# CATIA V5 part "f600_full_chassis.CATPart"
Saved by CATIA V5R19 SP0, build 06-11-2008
Part number: F600-2000000_AllCATPart
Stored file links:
  E:\F600-Full Chassis.CATPart
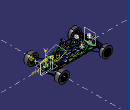
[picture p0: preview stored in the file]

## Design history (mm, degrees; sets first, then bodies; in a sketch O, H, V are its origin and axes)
Set1
  3DDatum1 "Solid.1"
  3DDatum2 "Solid.2"
Set2 "Front Suspension ASM\\RC-FRONT LOWER CONTROL ARM\\Hardpoints link with layout"
  Point1 "Lwr ball jt": stored without definition
  Point2 "LCA frnt bush": stored without definition
  Point3 "LCA rear bush": stored without definition
  Point4 "Shock lwr bush": stored without definition
  Point5 "Push rod lower point": stored without definition
Set3 "Front Suspension ASM\\Bell Crank\\Hardpoints link with seed part"
  Point6 "Shock lwr bush": stored without definition
  Point7 "Bell Crank Pivot": stored without definition
  Point8 "Push rod upper point": stored without definition
Set4 "Rear Suspension\\RC-REAR SHOCK ABSORBER\\Hardpoints link with layout"
  Point9 "Shock upr bush": stored without definition
  Point10 "Shock lwr bush": stored without definition
  Line1 "Line.5": stored without definition
Set5 "Rear Suspension\\DRIVING SHAFT POSITION PARTS\\Hardpoints link with layout"
  Point11 "drive_shaft_inner_point": stored without definition
  Point12 "Wheel Center": stored without definition
Set6 "Rear Suspension\\DRIVING SHAFT POSITION PARTS\\Geometrical Set.2"
  Line2 "Line.1": stored without definition
  Line3 "Line.2": stored without definition
  Line4 "Line.3": stored without definition
Set7 "Rear Suspension\\REAR-DAMPER-PUSH-ROD-SIN\\External References"
  Point13 "Push rod upr jt": stored without definition
  Point14 "Push rod lwr jt": stored without definition
Set8 "Steering System ASM\\XX---XXXXXXX---THREE SPOKE STEERING WHEEL\\Local Surface"
  DatumSurface1 "Sweep.1"
Set9 "Steering System ASM\\XX---XXXXXXX---STEERING MACHINE\\Isolated External References"
  Point15 "Inr Tierod ball jt": stored without definition
  Point16 "Rack Housing end": stored without definition
Set10 "Steering System ASM\\XX---XXXXXXX---STEERING MACHINE\\Temp Reference element"
  Point17 "Point.14": stored without definition
Set11 "Steering System ASM\\XX---XXXXXXX---STEERING MACHINE\\Reference Plane"
  Plane1 "Plane.2": stored without definition
Set12 "Kit_Buggy_Power Unit.1\\513MHA-1701500_ASM_AllCATPart.1\\Geometrical Set.1"
  Line5 "Axis.1": stored without definition
  Line6 "Axis.2": stored without definition
  Line7 "Axis.3": stored without definition
  Plane2 "Plane.1": stored without definition
  Plane3 "Plane.2": stored without definition
  Point18 "Intersect.1": stored without definition
  Plane4 "Plane.3": stored without definition
Set13 "Kit_Buggy_Power Unit.1\\motorpart.1\\Geometrical Set.1"
  Plane5 "Plane.1": stored without definition
Body1 (main body)
Body2 "Frame ASM\\Driving Case Front Lower Y Beam\\Driving Case Front Lower Y Beam"
  Solid1: solid without history
Body3 "Frame ASM\\Driving Case Middle Lower Y Beam\\Driving Case Middle Lower Y Beam"
  Solid2 "Solid.1": solid without history
Body4 "Frame ASM\\Driving Case Rear Lower Y Beam\\Driving Case Rear Lower Y Beam"
  Solid3 "Solid.1": solid without history
Body5 "Frame ASM\\Engine Room Middle Lower Y Beam-1\\Engine Room Middle Lower Y Beam-1"
  Solid4 "Solid.1": solid without history
Body6 "Frame ASM\\Engine Room Rear Lower Y Beam\\Engine Room Rear Lower Y Beam"
  Solid5 "Solid.1": solid without history
Body7 "Frame ASM\\Driving Case Lower Side Beam\\Driving Case Lower Side Beam"
  Solid6 "Solid.1": solid without history
Body8 "Frame ASM\\Engine Room Lower Side Beam\\Engine Room Lower Side Beam"
  Solid7 "Solid.1": solid without history
Body9 "Frame ASM\\Floor Rear Cross Stiffer\\Floor Rear Cross Stiffer"
  Solid8 "Solid.1": solid without history
Body10 "Frame ASM\\Safe Cage Rear Main Beam\\Safe Cage Rear Main Beam"
  Solid9 "Solid.1": solid without history
Body11 "Frame ASM\\Driving Case Rear Upper Y Beam\\Driving Case Rear Upper Y Beam"
  Solid10 "Solid.1": solid without history
Body12 "Frame ASM\\Safe Cage Rear Upper Cross Stiffer\\Safe Cage Rear Upper Cross Stiffer"
  Solid11 "Solid.2": solid without history
Body13 "Frame ASM\\Safe Cage Rear Lower Cross Stiffer\\Safe Cage Rear Lower Cross Stiffer"
  Solid12 "Solid.1": solid without history
Body14 "Frame ASM\\Safe Cage Front Main Frame\\Safe Cage Front Main Frame"
  Solid13 "Solid.1": solid without history
Body15 "Frame ASM\\Safe Cage Roof Y Beam\\Safe Cage Roof Y Beam"
  Solid14 "Solid.1": solid without history
Body16 "Frame ASM\\Safe Cage Front Y Beam\\Safe Cage Front Y Beam"
  Solid15 "Solid.1": solid without history
Body17 "Frame ASM\\Safe Cage Front Y Beam\\Bell Crank Support"
  Solid16 "Solid.1": solid without history
Body18 "Frame ASM\\Driving Case Front Upper Y Beam\\Driving Case Front Upper Y Beam"
  Solid17 "Solid.1": solid without history
Body19 "Frame ASM\\Engine Room Upper Side Beam\\Engine Room Upper Side Beam"
  Solid18 "Solid.1": solid without history
Body20 "Frame ASM\\Rear Back Bone Beam\\Rear Back Bone Beam"
  Solid19 "Solid.1": solid without history
Body21 "Frame ASM\\Rear Shocks Fixing Beam\\Rear Shocks Fixing Beam"
  Solid20 "Solid.4": solid without history
Body22 "Frame ASM\\Engine Room Middle Y Beam-3\\Engine Room Middle Y Beam-3"
  Solid21 "Solid.1": solid without history
Body23 "Frame ASM\\Engine Room Side Stiffer-3\\Engine Room Side Stiffer-3"
  Solid22 "Solid.1": solid without history
Body24 "Frame ASM\\Front Control Arm Lower Support\\Front Control Arm Lower Support"
  Solid23 "Solid.1": solid without history
Body25 "Frame ASM\\Driving Case Upper Side Beam\\Driving Case Upper Side Beam"
  Solid24 "Solid.1": solid without history
Body26 "Frame ASM\\Driving Case Front Z Beam\\Driving Case Front Z Beam"
  Solid25 "Solid.1": solid without history
Body27 "Frame ASM\\Driving Case Side Stiffer-1\\Driving Case Side Stiffer-1"
  Solid26 "Solid.1": solid without history
Body28 "Frame ASM\\Driving Case Middle Z Beam\\Driving Case Middle Z Beam"
  Solid27 "Solid.1": solid without history
Body29 "Frame ASM\\Driving Case Side Stiffer-2\\Driving Case Side Stiffer-2"
  Solid28 "Solid.1": solid without history
Body30 "Frame ASM\\Driving Case Side Stiffer-3\\Driving Case Side Stiffer-3"
  Solid29 "Solid.1": solid without history
Body31 "Frame ASM\\Safe Cage Front Stiffer-1\\Safe Cage Front Stiffer-1"
  Solid30 "Solid.1": solid without history
Body32 "Frame ASM\\Safe Cage Front Stiffer-2\\Safe Cage Front Stiffer-2"
  Solid31 "Solid.1": solid without history
Body33 "Frame ASM\\Safe Cage Front Stiffer-3\\Safe Cage Front Stiffer-3"
  Solid32 "Solid.1": solid without history
Body34 "Frame ASM\\Front Control Arm Support Stiffer\\Front Control Arm Support Stiffer"
  Solid33 "Solid.1": solid without history
Body35 "Frame ASM\\Shock Absorber Support\\Shock Absorber Support"
  Solid34 "Solid.1": solid without history
Body36 "Frame ASM\\Engine Room Middle Z Beam\\Engine Room Middle Z Beam"
  Solid35 "Solid.1": solid without history
Body37 "Frame ASM\\Engine Room Middle Y Beam-2\\Engine Room Middle Y Beam-2"
  Solid36 "Solid.1": solid without history
Body38 "Frame ASM\\Engine Room Side Sitffer-1\\Engine Room Side Sitffer-1"
  Solid37 "Solid.1": solid without history
Body39 "Frame ASM\\Final Gear Case Front Plate\\Final Gear Case Front Plate"
  Solid38 "Solid.1": solid without history
Body40 "Frame ASM\\Final Gear Case Rear Plate\\Final Gear Case Rear Plate"
  Solid39 "Solid.1": solid without history
Body41 "Frame ASM\\Engine Room Side Stiffer-2\\Engine Room Side Stiffer-2"
  Solid40 "Solid.1": solid without history
Body42 "Frame ASM\\Front Shock Absorber Fixing Bracket\\Front Shock Absorber Fixing Bracket"
  Solid41 "Solid.1": solid without history
Body43 "Frame ASM\\Floor\\Floor"
  Solid42 "Solid.1": solid without history
Body44 "Frame ASM\\Steering Column Fixing Bracket\\Steering Column Fixing Bracket"
  Solid43 "Solid.1": solid without history
Body45 "Frame ASM\\Symmetry of Safe Cage Front Stiffer-2.1\\Safe Cage Front Stiffer-2"
  Solid44 "Solid.1": solid without history
Body46 "Frame ASM\\Symmetry of Driving Case Front Z Beam.1\\Driving Case Front Z Beam"
  Solid45 "Solid.1": solid without history
Body47 "Frame ASM\\Symmetry of Driving Case Side Stiffer-1.1\\Driving Case Side Stiffer-1"
  Solid46 "Solid.1": solid without history
Body48 "Frame ASM\\Symmetry of Driving Case Middle Z Beam.1\\Driving Case Middle Z Beam"
  Solid47 "Solid.1": solid without history
Body49 "Frame ASM\\Symmetry of Driving Case Side Stiffer-2.1\\Driving Case Side Stiffer-2"
  Solid48 "Solid.1": solid without history
Body50 "Frame ASM\\Symmetry of Driving Case Side Stiffer-3.1\\Driving Case Side Stiffer-3"
  Solid49 "Solid.1": solid without history
Body51 "Frame ASM\\Symmetry of Floor Rear Cross Stiffer.1\\Floor Rear Cross Stiffer"
  Solid50 "Solid.1": solid without history
Body52 "Frame ASM\\Symmetry of Driving Case Lower Side Beam.1\\Driving Case Lower Side Beam"
  Solid51 "Solid.1": solid without history
Body53 "Frame ASM\\Symmetry of Engine Room Lower Side Beam.1\\Engine Room Lower Side Beam"
  Solid52 "Solid.1": solid without history
Body54 "Frame ASM\\Symmetry of Safe Cage Rear Upper Cross Stiffer.1\\Safe Cage Rear Upper Cross Stiffer"
  Solid53 "Solid.1": solid without history
Body55 "Frame ASM\\Symmetry of Safe Cage Rear Lower Cross Stiffer.1\\Safe Cage Rear Lower Cross Stiffer"
  Solid54 "Solid.1": solid without history
Body56 "Frame ASM\\Symmetry of Rear Back Bone Beam.1\\Rear Back Bone Beam"
  Solid55 "Solid.1": solid without history
Body57 "Frame ASM\\Symmetry of Engine Room Middle Z Beam.1\\Engine Room Middle Z Beam"
  Solid56 "Solid.1": solid without history
Body58 "Frame ASM\\Symmetry of Engine Room Side Stiffer-3.1\\Engine Room Side Stiffer-3"
  Solid57 "Solid.1": solid without history
Body59 "Frame ASM\\Symmetry of Rear Shocks Fixing Beam.1\\Rear Shocks Fixing Beam"
  Solid58 "Solid.1": solid without history
Body60 "Frame ASM\\Symmetry of Engine Room Side Stiffer-2.1\\Engine Room Side Stiffer-2"
  Solid59 "Solid.1": solid without history
Body61 "Frame ASM\\Symmetry of Engine Room Side Sitffer-1.1\\Engine Room Side Sitffer-1"
  Solid60 "Solid.1": solid without history
Body62 "Frame ASM\\Symmetry of Steering Column Fixing Bracket.1\\Steering Column Fixing Bracket"
  Solid61 "Solid.1": solid without history
Body63 "Frame ASM\\Symmetry of Safe Cage Front Stiffer-1.1\\Safe Cage Front Stiffer-1"
  Solid62 "Solid.1": solid without history
Body64 "Frame ASM\\Symmetry of Shock Absorber Support.1\\Shock Absorber Support"
  Solid63 "Solid.1": solid without history
Body65 "Front Suspension ASM\\RC-FRONT LOWER CONTROL ARM\\Outer Bush"
  Solid64 "Solid.1": solid without history
Body66 "Front Suspension ASM\\RC-FRONT LOWER CONTROL ARM\\Lower Front Arm"
  Solid65 "Solid.1": solid without history
Body67 "Front Suspension ASM\\RC-FRONT LOWER CONTROL ARM\\Lower Rear Arm"
  Solid66 "Solid.1": solid without history
Body68 "Front Suspension ASM\\RC-FRONT LOWER CONTROL ARM\\Rear Bush"
  Solid67 "Solid.1": solid without history
Body69 "Front Suspension ASM\\RC-FRONT LOWER CONTROL ARM\\Front Bush"
  Solid68 "Solid.3": solid without history
Body70 "Front Suspension ASM\\RC-FRONT LOWER CONTROL ARM\\Shock Absorber Fixing Bracket"
  Solid69 "Solid.1": solid without history
Body71 "Front Suspension ASM\\RC-FRONT STEERING KNUCKLE\\Main Body"
  Solid70 "Solid.1": solid without history
Body72 "Front Suspension ASM\\RC-FRONT STEERING KNUCKLE\\Bearing House"
  Solid71 "Solid.1": solid without history
Body73 "Front Suspension ASM\\RC-FRONT STEERING KNUCKLE\\Body.9"
  Solid72 "Solid.1": solid without history
Body74 "Front Suspension ASM\\13-6Inch Formula Rim\\Body.1"
  Solid73 "Solid.1": solid without history
Body75 "Front Suspension ASM\\13-6Inch Formula Rim\\Body.2"
  Solid74 "Solid.1": solid without history
Body76 "Front Suspension ASM\\RC-FRONT SHOCK ABSORBER ASM\\Upper Tube"
  Solid75 "Solid.1": solid without history
Body77 "Front Suspension ASM\\RC-FRONT SHOCK ABSORBER ASM\\Lower Tube"
  Solid76 "Solid.1": solid without history
Body78 "Front Suspension ASM\\RC-FRONT SHOCK ABSORBER ASM\\Upper Spring Seat"
  Solid77 "Solid.1": solid without history
Body79 "Front Suspension ASM\\RC-FRONT SHOCK ABSORBER ASM\\Spring"
  Solid78 "Solid.1": solid without history
Body80 "Front Suspension ASM\\RC-FRONT SHOCK ABSORBER ASM\\Upper Fixing Tube"
  Solid79 "Solid.1": solid without history
Body81 "Front Suspension ASM\\RC-FRONT SHOCK ABSORBER ASM\\Lower FixingTube"
  Solid80 "Solid.1": solid without history
Body82 "Front Suspension ASM\\ATV-23-7-10\\Body.1"
  Solid81 "Solid.1": solid without history
Body83 "Front Suspension ASM\\7205B.1\\Inner Roller"
  Solid82 "Solid.1": solid without history
Body84 "Front Suspension ASM\\7205B.1\\Ball"
  Solid83 "Solid.1": solid without history
Body85 "Front Suspension ASM\\7205B.1\\Outer Roller"
  Solid84 "Solid.1": solid without history
Body86 "Front Suspension ASM\\7205B.2\\Inner Roller"
  Solid85 "Solid.1": solid without history
Body87 "Front Suspension ASM\\7205B.2\\Ball"
  Solid86 "Solid.1": solid without history
Body88 "Front Suspension ASM\\7205B.2\\Outer Roller"
  Solid87 "Solid.1": solid without history
Body89 "Front Suspension ASM\\ISO 8675 NUT M20x1.5 STEEL GRADE C HEXAGON THIN METRIC FINE.1\\BodyPartBody"
  Solid88 "Solid.1": solid without history
Body90 "Front Suspension ASM\\Front Hub\\HUB"
  Solid89 "Solid.1": solid without history
Body91 "Front Suspension ASM\\Front Rotor\\Body.1"
  Solid90 "Solid.1": solid without history
Body92 "Front Suspension ASM\\Ball Joint Shell.3\\Outer Ball Joint Shell"
  Solid91 "Solid.1": solid without history
Body93 "Front Suspension ASM\\Ball Joint Sphere.3\\BJ-Sphere"
  Solid92 "Solid.4": solid without history
Body94 "Front Suspension ASM\\RC-1000003.1\\Front Arm"
  Solid93 "Solid.1": solid without history
Body95 "Front Suspension ASM\\RC-1000003.1\\Rear Arm"
  Solid94 "Solid.1": solid without history
Body96 "Front Suspension ASM\\RC-1000003.1\\Middle tube"
  Solid95 "Solid.1": solid without history
Body97 "Front Suspension ASM\\RC-1000003.1\\Outer Ball Joint Shell"
  Solid96 "Solid.2": solid without history
Body98 "Front Suspension ASM\\Push Rod\\Push Rod"
  Solid97 "Solid.1": solid without history
Body99 "Front Suspension ASM\\Bell Crank\\Bell Crank"
  Solid98 "Solid.1": solid without history
Body100 "Front Suspension ASM\\Bell Crank\\Pivot Tube"
  Solid99 "Solid.1": solid without history
Body101 "Front Suspension ASM\\Bell Crank\\Push_Link"
  Solid100 "Solid.1": solid without history
Body102 "Rear Suspension\\RC-REAR UPPER CONTROL ARM\\Outer Ball Joint Shell"
  Solid101 "Solid.1": solid without history
Body103 "Rear Suspension\\RC-REAR UPPER CONTROL ARM\\Front Arm"
  Solid102 "Solid.9": solid without history
Body104 "Rear Suspension\\RC-REAR UPPER CONTROL ARM\\Rear Arm"
  Solid103 "Solid.1": solid without history
Body105 "Rear Suspension\\RC-REAR UPPER CONTROL ARM\\Outer Tube"
  Solid104 "Solid.22": solid without history
Body106 "Rear Suspension\\RC-REAR LOWER CONTROL ARM.1\\Outer Ball Joint Shell"
  Solid105 "Solid.1": solid without history
Body107 "Rear Suspension\\RC-REAR LOWER CONTROL ARM.1\\Front Arm"
  Solid106 "Solid.1": solid without history
Body108 "Rear Suspension\\RC-REAR LOWER CONTROL ARM.1\\Rear_Arm"
  Solid107 "Solid.1": solid without history
Body109 "Rear Suspension\\RC-REAR LOWER CONTROL ARM.1\\Rear Arm 2"
  Solid108 "Solid.1": solid without history
Body110 "Rear Suspension\\RC-REAR LOWER CONTROL ARM.1\\Middle Tube"
  Solid109 "Solid.1": solid without history
Body111 "Rear Suspension\\RC-REAR LOWER CONTROL ARM.1\\Outer Tube"
  Solid110 "Solid.34": solid without history
Body112 "Rear Suspension\\RC-REAR LOWER CONTROL ARM.1\\Outer Ball Joint Shell"
  Solid111 "Solid.1": solid without history
Body113 "Rear Suspension\\RC-REAR KNUCKLE\\Mian Body"
  Solid112 "Solid.1": solid without history
Body114 "Rear Suspension\\RC-REAR KNUCKLE\\Bearing House"
  Solid113 "Solid.1": solid without history
Body115 "Rear Suspension\\RC-REAR KNUCKLE\\Lower Tube"
  Solid114 "Solid.1": solid without history
Body116 "Rear Suspension\\RC-REAR SHOCK ABSORBER\\Upper Tube"
  Solid115 "Solid.2": solid without history
Body117 "Rear Suspension\\RC-REAR SHOCK ABSORBER\\Lower Tube"
  Solid116 "Solid.6": solid without history
Body118 "Rear Suspension\\RC-REAR SHOCK ABSORBER\\Upper Spring Seat"
  Solid117 "Solid.9": solid without history
Body119 "Rear Suspension\\RC-REAR SHOCK ABSORBER\\Spring"
  Solid118 "Solid.13": solid without history
Body120 "Rear Suspension\\RC-REAR SHOCK ABSORBER\\Upper Fixing Tube"
  Solid119 "Solid.14": solid without history
Body121 "Rear Suspension\\RC-REAR SHOCK ABSORBER\\Lower FixingTube"
  Solid120 "Solid.15": solid without history
Body122 "Rear Suspension\\WHEEL RIM\\Body.1"
  Solid121 "Solid.1": solid without history
Body123 "Rear Suspension\\WHEEL RIM\\Body.2"
  Solid122 "Solid.1": solid without history
Body124 "Rear Suspension\\XX-205-45-R16\\Body.1"
  Solid123 "Solid.1": solid without history
Body125 "Rear Suspension\\B21-3001017.1\\Body.1"
  Solid124 "Solid.1": solid without history
Body126 "Rear Suspension\\B11-2203205.1\\Body.1"
  Solid125 "Solid.1": solid without history
Body127 "Rear Suspension\\CVJT.1\\Body.1"
  Solid126 "Solid.1": solid without history
Body128 "Rear Suspension\\CVJT.1\\Dust Cover"
  Solid127 "Solid.1": solid without history
Body129 "Rear Suspension\\INNER CVJT.1\\Body.1"
  Solid128 "Solid.1": solid without history
Body130 "Rear Suspension\\INNER CVJT.1\\DustCover"
  Solid129 "Solid.1": solid without history
Body131 "Rear Suspension\\Dirving Shaft Middle Column.1\\Body.1"
  Solid130 "Solid.1": solid without history
Body132 "Rear Suspension\\Dirving Shaft Middle Column.1\\Dust Cover"
  Solid131 "Solid.1": solid without history
Body133 "Rear Suspension\\REAR-DAMPER-PUSH-ROD-SIN\\Tube"
  Solid132 "Solid.1": solid without history
Body134 "Rear Suspension\\REAR-DAMPER-BELL-CRANK-LH\\Bell Crank"
  Solid133 "Solid.1": solid without history
Body135 "Rear Suspension\\REAR-DAMPER-BELL-CRANK-LH\\Rotation Tube"
  Solid134 "Solid.1": solid without history
Body136 "Steering System ASM\\XX---XXXXXXX---THREE SPOKE STEERING WHEEL\\SPOKE"
  Solid135 "Solid.1": solid without history
Body137 "Steering System ASM\\XX---XXXXXXX---STEERING COLUMN\\Body.31"
  Solid136 "Solid.1": solid without history
Body138 "Steering System ASM\\XX---XXXXXXX---STEERING MACHINE\\PartBody"
  Solid137 "Solid.1": solid without history
Body139 "Steering System ASM\\XX---XXXXXXX---STEERING ROD\\PartBody"
  Solid138 "Solid.1": solid without history
Body140 "Steering System ASM\\Symmetry of XX---XXXXXXX---STEERING ROD.1\\PartBody"
  Solid139 "Solid.1": solid without history
Body141 "Steering System ASM\\UNIVERSAL JOINT FORK.1\\PartBody"
  Solid140 "Solid.1": solid without history
Body142 "Steering System ASM\\UNIVERSAL JOINT FORK-2.2\\PartBody"
  Solid141 "Solid.1": solid without history
Body143 "Steering System ASM\\RC-8000001-1.1\\PartBody"
  Solid142 "Solid.1": solid without history
Body144 "Steering System ASM\\RC-8000001-1.1\\Body.2"
  Solid143 "Solid.1": solid without history
Body145 "Steering System ASM\\RC-8000001-1.2\\PartBody"
  Solid144 "Solid.1": solid without history
Body146 "Steering System ASM\\RC-8000001-1.2\\Body.2"
  Solid145 "Solid.1": solid without history
Body147 "Steering System ASM\\ANGLE CONTACTED BALL BEARING-7003C\\Inner Roller"
  Solid146 "Solid.1": solid without history
Body148 "Steering System ASM\\ANGLE CONTACTED BALL BEARING-7003C\\Ball"
  Solid147 "Solid.1": solid without history
Body149 "Steering System ASM\\ANGLE CONTACTED BALL BEARING-7003C\\Outer Roller"
  Solid148 "Solid.1": solid without history
Body150 "Steering System ASM\\ANGLE CONTACTED BALL BEARING-7003C.1\\Inner Roller"
  Solid149 "Solid.1": solid without history
Body151 "Steering System ASM\\ANGLE CONTACTED BALL BEARING-7003C.1\\Ball"
  Solid150 "Solid.1": solid without history
Body152 "Steering System ASM\\ANGLE CONTACTED BALL BEARING-7003C.1\\Outer Roller"
  Solid151 "Solid.1": solid without history
Body153 "Steering System ASM\\BEARING HOUSE\\PartBody"
  Solid152 "Solid.1": solid without history
Body154 "Steering System ASM\\BEARING HOUSE.1\\PartBody"
  Solid153 "Solid.1": solid without history
Body155 "Kit_Buggy_Power Unit.1\\Differentation.1\\Chain Wheel"
  Solid154 "Solid.1": solid without history
Body156 "Kit_Buggy_Power Unit.1\\Differentation.1\\Chain"
  Solid155 "Solid.1": solid without history
Body157 "Kit_Buggy_Power Unit.1\\Differentation.1\\Connecting Flange"
  Solid156 "Solid.1": solid without history
  Sketch1 "Sketch.18", origin (2049.9819, -110.2005, 10.7859), H (-1, 0, 0), V (0, 0, 1), geometry linked from another document
Body158 "Kit_Buggy_Power Unit.1\\513MHA-1701500_ASM_AllCATPart.1\\188\\MANIFOLD_SOLID_BREP #2629297"
  Solid157 "Solid.1": solid without history
Body159 "Kit_Buggy_Power Unit.1\\513MHA-1701500_ASM_AllCATPart.1\\189\\MANIFOLD_SOLID_BREP #2647029"
  Solid158 "Solid.1": solid without history
Body160 "Kit_Buggy_Power Unit.1\\513MHA-1701500_ASM_AllCATPart.1\\190\\MANIFOLD_SOLID_BREP #2629297"
  Solid159 "Solid.1": solid without history
Body161 "Kit_Buggy_Power Unit.1\\513MHA-1701500_ASM_AllCATPart.1\\191\\MANIFOLD_SOLID_BREP #2647029"
  Solid160 "Solid.1": solid without history
Body162 "Kit_Buggy_Power Unit.1\\513MHA-1701500_ASM_AllCATPart.1\\192\\MANIFOLD_SOLID_BREP #2647293"
  Solid161 "Solid.1": solid without history
Body163 "Kit_Buggy_Power Unit.1\\513MHA-1701500_ASM_AllCATPart.1\\193\\MANIFOLD_SOLID_BREP #2647293"
  Solid162 "Solid.1": solid without history
Body164 "Kit_Buggy_Power Unit.1\\513MHA-1701500_ASM_AllCATPart.1\\194\\MANIFOLD_SOLID_BREP #2656548"
  Solid163 "Solid.1": solid without history
Body165 "Kit_Buggy_Power Unit.1\\513MHA-1701500_ASM_AllCATPart.1\\195\\MANIFOLD_SOLID_BREP #2656548"
  Solid164 "Solid.1": solid without history
Body166 "Kit_Buggy_Power Unit.1\\513MHA-1701500_ASM_AllCATPart.1\\196\\MANIFOLD_SOLID_BREP #2657716"
  Solid165 "Solid.1": solid without history
Body167 "Kit_Buggy_Power Unit.1\\513MHA-1701500_ASM_AllCATPart.1\\197\\MANIFOLD_SOLID_BREP #2658366"
  Solid166 "Solid.1": solid without history
Body168 "Kit_Buggy_Power Unit.1\\513MHA-1701500_ASM_AllCATPart.1\\211\\207\\MANIFOLD_SOLID_BREP #2711857"
  Solid167 "Solid.1": solid without history
Body169 "Kit_Buggy_Power Unit.1\\513MHA-1701500_ASM_AllCATPart.1\\211\\208\\MANIFOLD_SOLID_BREP #2712359"
  Solid168 "Solid.1": solid without history
Body170 "Kit_Buggy_Power Unit.1\\513MHA-1701500_ASM_AllCATPart.1\\211\\210\\MANIFOLD_SOLID_BREP #2714242"
  Solid169 "Solid.1": solid without history
Body171 "Kit_Buggy_Power Unit.1\\513MHA-1701500_ASM_AllCATPart.1\\212\\207\\MANIFOLD_SOLID_BREP #2711857"
  Solid170 "Solid.1": solid without history
Body172 "Kit_Buggy_Power Unit.1\\513MHA-1701500_ASM_AllCATPart.1\\212\\208\\MANIFOLD_SOLID_BREP #2712359"
  Solid171 "Solid.1": solid without history
Body173 "Kit_Buggy_Power Unit.1\\513MHA-1701500_ASM_AllCATPart.1\\212\\209\\MANIFOLD_SOLID_BREP #2712579"
  Solid172 "Solid.1": solid without history
Body174 "Kit_Buggy_Power Unit.1\\513MHA-1701500_ASM_AllCATPart.1\\212\\209\\MANIFOLD_SOLID_BREP #2712767"
  Solid173 "Solid.1": solid without history
Body175 "Kit_Buggy_Power Unit.1\\513MHA-1701500_ASM_AllCATPart.1\\212\\209\\MANIFOLD_SOLID_BREP #2712955"
  Solid174 "Solid.1": solid without history
Body176 "Kit_Buggy_Power Unit.1\\513MHA-1701500_ASM_AllCATPart.1\\212\\209\\MANIFOLD_SOLID_BREP #2713143"
  Solid175 "Solid.1": solid without history
Body177 "Kit_Buggy_Power Unit.1\\513MHA-1701500_ASM_AllCATPart.1\\212\\210\\MANIFOLD_SOLID_BREP #2714242"
  Solid176 "Solid.1": solid without history
Body178 "Kit_Buggy_Power Unit.1\\513MHA-1701500_ASM_AllCATPart.1\\Left Fixing Flange"
  Solid177 "Solid.1": solid without history
  Sketch2 "Sketch.1", origin (2049.9819, -102.0792, 10.7859), H (1, 0, 0), V (0, 0, 1), geometry linked from another document
Body179 "Kit_Buggy_Power Unit.1\\513MHA-1701500_ASM_AllCATPart.1\\Rear Braking Disc"
  Solid178 "Solid.1": solid without history
Body180 "Kit_Buggy_Power Unit.1\\513MHA-1701500_ASM_AllCATPart.1\\Left Frame"
  Solid179 "Solid.1": solid without history
Body181 "Kit_Buggy_Power Unit.1\\513MHA-1701500_ASM_AllCATPart.1\\Right Frame"
  Solid180 "Solid.1": solid without history
Body182 "Kit_Buggy_Power Unit.1\\513MHA-1701500_ASM_AllCATPart.1\\Frame Link Tube"
  Solid181 "Solid.1": solid without history
Body183 "Kit_Buggy_Power Unit.1\\513MHA-1701500_ASM_AllCATPart.1\\New Shell-Left"
  Solid182 "Solid.1": solid without history
Body184 "Kit_Buggy_Power Unit.1\\513MHA-1701500_ASM_AllCATPart.1\\New Shell-Right"
  Solid183 "Solid.22": solid without history
Body185 "Kit_Buggy_Power Unit.1\\motorpart.1\\Brep With Voids.1"
  Solid184 "Solid.1": solid without history
Body186 "Kit_Buggy_Power Unit.1\\motorpart.1\\PartBody.2"
  Solid185 "Solid.1": solid without history
Body187 "Kit_Buggy_Power Unit.1\\motorpart.1\\PartBody.4"
  Solid186 "Solid.1": solid without history
Body188 "Kit_Buggy_Power Unit.1\\motorpart.1\\PartBody.5"
  Solid187 "Solid.1": solid without history
Body189 "Kit_Buggy_Power Unit.1\\motorpart.1\\PartBody.6"
  Solid188 "Solid.1": solid without history
Body190 "Kit_Buggy_Power Unit.1\\motorpart.1\\PartBody.7"
  Solid189 "Solid.1": solid without history
Body191 "Kit_Buggy_Power Unit.1\\motorpart.1\\PartBody.8"
  Solid190 "Solid.1": solid without history
Body192 "Kit_Buggy_Power Unit.1\\motorpart.1\\New Sump"
  Solid191 "Solid.1": solid without history
Body193 "Symmetry of Rear Suspension.1\\Symmetry of RC-REAR UPPER CONTROL ARM.1\\Outer Ball Joint Shell"
  Solid192 "Solid.1": solid without history
Body194 "Symmetry of Rear Suspension.1\\Symmetry of RC-REAR UPPER CONTROL ARM.1\\Front Arm"
  Solid193 "Solid.2": solid without history
Body195 "Symmetry of Rear Suspension.1\\Symmetry of RC-REAR UPPER CONTROL ARM.1\\Rear Arm"
  Solid194 "Solid.3": solid without history
Body196 "Symmetry of Rear Suspension.1\\Symmetry of RC-REAR UPPER CONTROL ARM.1\\Outer Tube"
  Solid195 "Solid.4": solid without history
Body197 "Symmetry of Rear Suspension.1\\Symmetry of RC-REAR LOWER CONTROL ARM.1.1\\Outer Ball Joint Shell"
  Solid196 "Solid.1": solid without history
Body198 "Symmetry of Rear Suspension.1\\Symmetry of RC-REAR LOWER CONTROL ARM.1.1\\Front Arm"
  Solid197 "Solid.2": solid without history
Body199 "Symmetry of Rear Suspension.1\\Symmetry of RC-REAR LOWER CONTROL ARM.1.1\\Rear_Arm"
  Solid198 "Solid.3": solid without history
Body200 "Symmetry of Rear Suspension.1\\Symmetry of RC-REAR LOWER CONTROL ARM.1.1\\Rear Arm 2"
  Solid199 "Solid.4": solid without history
Body201 "Symmetry of Rear Suspension.1\\Symmetry of RC-REAR LOWER CONTROL ARM.1.1\\Middle Tube"
  Solid200 "Solid.5": solid without history
Body202 "Symmetry of Rear Suspension.1\\Symmetry of RC-REAR LOWER CONTROL ARM.1.1\\Outer Tube"
  Solid201 "Solid.6": solid without history
Body203 "Symmetry of Rear Suspension.1\\Symmetry of RC-REAR LOWER CONTROL ARM.1.1\\Outer Ball Joint Shell"
  Solid202 "Solid.7": solid without history
Body204 "Symmetry of Rear Suspension.1\\Symmetry of RC-REAR KNUCKLE.1\\Mian Body"
  Solid203 "Solid.1": solid without history
Body205 "Symmetry of Rear Suspension.1\\Symmetry of RC-REAR KNUCKLE.1\\Bearing House"
  Solid204 "Solid.2": solid without history
Body206 "Symmetry of Rear Suspension.1\\Symmetry of RC-REAR KNUCKLE.1\\Lower Tube"
  Solid205 "Solid.3": solid without history
Body207 "Symmetry of Rear Suspension.1\\Symmetry of RC-REAR SHOCK ABSORBER.1\\Upper Tube"
  Solid206 "Solid.1": solid without history
Body208 "Symmetry of Rear Suspension.1\\Symmetry of RC-REAR SHOCK ABSORBER.1\\Lower Tube"
  Solid207 "Solid.2": solid without history
Body209 "Symmetry of Rear Suspension.1\\Symmetry of RC-REAR SHOCK ABSORBER.1\\Upper Spring Seat"
  Solid208 "Solid.3": solid without history
Body210 "Symmetry of Rear Suspension.1\\Symmetry of RC-REAR SHOCK ABSORBER.1\\Spring"
  Solid209 "Solid.4": solid without history
Body211 "Symmetry of Rear Suspension.1\\Symmetry of RC-REAR SHOCK ABSORBER.1\\Upper Fixing Tube"
  Solid210 "Solid.5": solid without history
Body212 "Symmetry of Rear Suspension.1\\Symmetry of RC-REAR SHOCK ABSORBER.1\\Lower FixingTube"
  Solid211 "Solid.6": solid without history
Body213 "Symmetry of Rear Suspension.1\\Symmetry of WHEEL RIM.1\\Body.1"
  Solid212 "Solid.1": solid without history
Body214 "Symmetry of Rear Suspension.1\\Symmetry of WHEEL RIM.1\\Body.2"
  Solid213 "Solid.2": solid without history
Body215 "Symmetry of Rear Suspension.1\\Symmetry of XX-205-45-R16.1\\Body.1"
  Solid214 "Solid.1": solid without history
Body216 "Symmetry of Rear Suspension.1\\Symmetry of B21-3001017.1.1\\Body.1"
  Solid215 "Solid.1": solid without history
Body217 "Symmetry of Rear Suspension.1\\Symmetry of B11-2203205.1.1\\Body.1"
  Solid216 "Solid.1": solid without history
Body218 "Symmetry of Rear Suspension.1\\Symmetry of CVJT.1.1\\Body.1"
  Solid217 "Solid.1": solid without history
Body219 "Symmetry of Rear Suspension.1\\Symmetry of CVJT.1.1\\Dust Cover"
  Solid218 "Solid.2": solid without history
Body220 "Symmetry of Rear Suspension.1\\Symmetry of INNER CVJT.1.1\\Body.1"
  Solid219 "Solid.1": solid without history
Body221 "Symmetry of Rear Suspension.1\\Symmetry of INNER CVJT.1.1\\DustCover"
  Solid220 "Solid.2": solid without history
Body222 "Symmetry of Rear Suspension.1\\Symmetry of Dirving Shaft Middle Column.1.1\\Body.1"
  Solid221 "Solid.1": solid without history
Body223 "Symmetry of Rear Suspension.1\\Symmetry of Dirving Shaft Middle Column.1.1\\Dust Cover"
  Solid222 "Solid.2": solid without history
Body224 "Symmetry of Rear Suspension.1\\Symmetry of REAR-DAMPER-PUSH-ROD-SIN.1\\Tube"
  Solid223 "Solid.1": solid without history
Body225 "Symmetry of Rear Suspension.1\\Symmetry of REAR-DAMPER-BELL-CRANK-LH.1\\Bell Crank"
  Solid224 "Solid.1": solid without history
Body226 "Symmetry of Rear Suspension.1\\Symmetry of REAR-DAMPER-BELL-CRANK-LH.1\\Rotation Tube"
  Solid225 "Solid.2": solid without history
Body227 "Symmetry of Front Suspension ASM.1\\Symmetry of RC-FRONT LOWER CONTROL ARM.1\\Outer Bush"
  Solid226 "Solid.1": solid without history
Body228 "Symmetry of Front Suspension ASM.1\\Symmetry of RC-FRONT LOWER CONTROL ARM.1\\Lower Front Arm"
  Solid227 "Solid.2": solid without history
Body229 "Symmetry of Front Suspension ASM.1\\Symmetry of RC-FRONT LOWER CONTROL ARM.1\\Lower Rear Arm"
  Solid228 "Solid.3": solid without history
Body230 "Symmetry of Front Suspension ASM.1\\Symmetry of RC-FRONT LOWER CONTROL ARM.1\\Rear Bush"
  Solid229 "Solid.4": solid without history
Body231 "Symmetry of Front Suspension ASM.1\\Symmetry of RC-FRONT LOWER CONTROL ARM.1\\Front Bush"
  Solid230 "Solid.5": solid without history
Body232 "Symmetry of Front Suspension ASM.1\\Symmetry of RC-FRONT LOWER CONTROL ARM.1\\Shock Absorber Fixing Bracket"
  Solid231 "Solid.6": solid without history
Body233 "Symmetry of Front Suspension ASM.1\\Symmetry of RC-FRONT STEERING KNUCKLE.1\\Main Body"
  Solid232 "Solid.1": solid without history
Body234 "Symmetry of Front Suspension ASM.1\\Symmetry of RC-FRONT STEERING KNUCKLE.1\\Bearing House"
  Solid233 "Solid.4": solid without history
Body235 "Symmetry of Front Suspension ASM.1\\Symmetry of RC-FRONT STEERING KNUCKLE.1\\Body.9"
  Solid234 "Solid.6": solid without history
Body236 "Symmetry of Front Suspension ASM.1\\Symmetry of 13-6Inch Formula Rim.1\\Body.1"
  Solid235 "Solid.1": solid without history
Body237 "Symmetry of Front Suspension ASM.1\\Symmetry of 13-6Inch Formula Rim.1\\Body.2"
  Solid236 "Solid.2": solid without history
Body238 "Symmetry of Front Suspension ASM.1\\Symmetry of ATV-23-7-10.1\\Body.1"
  Solid237 "Solid.1": solid without history
Body239 "Symmetry of Front Suspension ASM.1\\Symmetry of 7205B.1.1\\Inner Roller"
  Solid238 "Solid.1": solid without history
Body240 "Symmetry of Front Suspension ASM.1\\Symmetry of 7205B.1.1\\Ball"
  Solid239 "Solid.2": solid without history
Body241 "Symmetry of Front Suspension ASM.1\\Symmetry of 7205B.1.1\\Outer Roller"
  Solid240 "Solid.3": solid without history
Body242 "Symmetry of Front Suspension ASM.1\\Symmetry of 7205B.2.1\\Inner Roller"
  Solid241 "Solid.1": solid without history
Body243 "Symmetry of Front Suspension ASM.1\\Symmetry of 7205B.2.1\\Ball"
  Solid242 "Solid.2": solid without history
Body244 "Symmetry of Front Suspension ASM.1\\Symmetry of 7205B.2.1\\Outer Roller"
  Solid243 "Solid.3": solid without history
Body245 "Symmetry of Front Suspension ASM.1\\Symmetry of ISO 8675 NUT M20x1.5 STEEL GRADE C HEXAGON THIN METRIC FINE.1.1\\BodyPartBody"
  Solid244 "Solid.1": solid without history
Body246 "Symmetry of Front Suspension ASM.1\\Symmetry of Front Hub.1\\HUB"
  Solid245 "Solid.1": solid without history
Body247 "Symmetry of Front Suspension ASM.1\\Symmetry of Front Rotor.1\\Body.1"
  Solid246 "Solid.1": solid without history
Body248 "Symmetry of Front Suspension ASM.1\\Symmetry of Ball Joint Shell.3.1\\Outer Ball Joint Shell"
  Solid247 "Solid.1": solid without history
Body249 "Symmetry of Front Suspension ASM.1\\Symmetry of Ball Joint Sphere.3.1\\BJ-Sphere"
  Solid248 "Solid.1": solid without history
Body250 "Symmetry of Front Suspension ASM.1\\Symmetry of RC-1000003.1.1\\Front Arm"
  Solid249 "Solid.1": solid without history
Body251 "Symmetry of Front Suspension ASM.1\\Symmetry of RC-1000003.1.1\\Rear Arm"
  Solid250 "Solid.2": solid without history
Body252 "Symmetry of Front Suspension ASM.1\\Symmetry of RC-1000003.1.1\\Middle tube"
  Solid251 "Solid.3": solid without history
Body253 "Symmetry of Front Suspension ASM.1\\Symmetry of RC-1000003.1.1\\Outer Ball Joint Shell"
  Solid252 "Solid.4": solid without history
Body254 "Symmetry of Front Suspension ASM.1\\Symmetry of Push Rod.1\\Push Rod"
  Solid253 "Solid.1": solid without history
